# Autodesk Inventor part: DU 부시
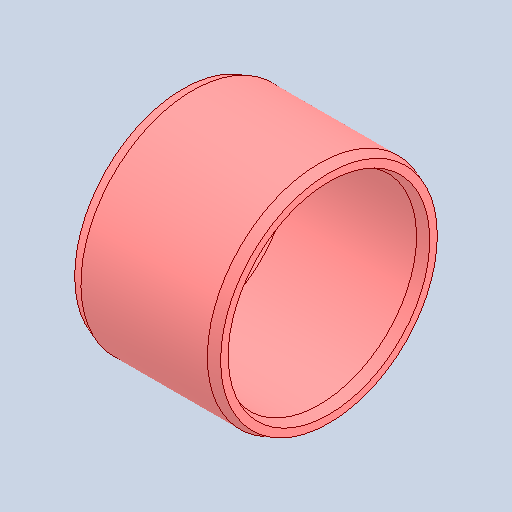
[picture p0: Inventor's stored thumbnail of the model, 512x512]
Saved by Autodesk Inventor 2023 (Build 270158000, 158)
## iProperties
Created: 2025-10
Part Number: DU 부시
Material: 스테인리스스틸
Document SubType Name: Modeling
Designer: home
Density: 8 g/cm^3
Appearance: 기본값
Author: jhkim
Sending System: Autodesk Inventor 2026
Preprocessor: ST-DEVELOPER v20.1
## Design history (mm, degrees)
feature "솔리드1"
node "솔리드2"
